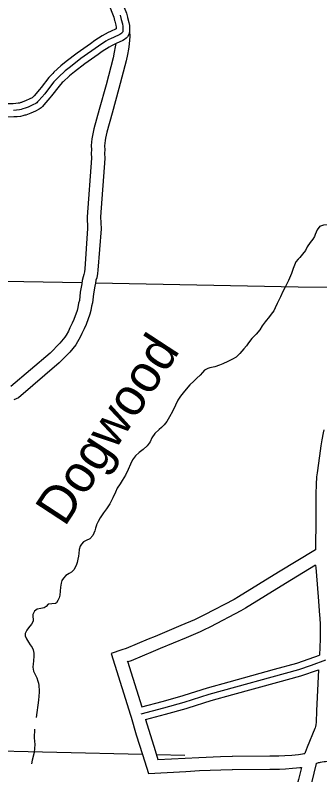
# Model space of a CAD drawing. Extents: x 1373094 to 1376427, y 1168361 to 1170494.
# Drawn here: x 1373788 to 1373845.2, y 1170254.2 to 1170397.1 of the extents above; entities that cross this region are included whole.
import ezdxf

# ---------------------------------------------------------------- set-up
doc = ezdxf.new("R2010")
doc.units = 0
doc.layers.add('R_Axis', color=7, linetype='Continuous')

msp = doc.modelspace()

# ---------------------------------------------------------------- linework, layer by layer
at = {"layer": 'R_Axis'}
for points in [[(1373806.18, 1170404.85), (1373806.33, 1170404.33), (1373807.4, 1170401.21), (1373808.14, 1170399.35), (1373808.44, 1170398.55), (1373808.85, 1170397.47), (1373809.05, 1170396.72)], [(1373803.7, 1170404.54), (1373803.72, 1170404.34), (1373803.95, 1170403.57), (1373805.05, 1170400.34), (1373805.81, 1170398.45), (1373806.1, 1170397.66), (1373806.47, 1170396.69), (1373806.64, 1170396.07)], [(1373807.66, 1170397.08), (1373807.87, 1170396.29), (1373808.1, 1170395.43), (1373808.17, 1170394.97), (1373808.19, 1170394.69), (1373808.21, 1170394.39), (1373808.2, 1170394.19), (1373808.19, 1170394.07), (1373808.16, 1170393.93), (1373808.07, 1170393.79), (1373807.98, 1170393.69), (1373807.79, 1170393.55), (1373807.6, 1170393.43), (1373806.4, 1170392.9), (1373805.99, 1170392.7), (1373805.44, 1170392.42), (1373804.98, 1170392.16), (1373803.61, 1170391.27), (1373800.32, 1170388.91), (1373798.32, 1170387.39), (1373797.33, 1170386.59), (1373796.09, 1170385.44), (1373795.24, 1170384.56), (1373793.82, 1170382.71), (1373793.5, 1170382.31)], [(1373809.05, 1170396.72), (1373809.08, 1170396.61), (1373809.33, 1170395.68), (1373809.41, 1170395.11), (1373809.44, 1170394.78), (1373809.46, 1170394.4), (1373809.45, 1170394.13), (1373809.43, 1170393.87), (1373809.32, 1170393.43), (1373809.07, 1170393.03), (1373808.82, 1170392.76), (1373808.49, 1170392.51), (1373808.18, 1170392.32), (1373806.93, 1170391.77), (1373806.54, 1170391.58), (1373806.03, 1170391.32), (1373805.63, 1170391.09), (1373804.32, 1170390.23), (1373803.54, 1170389.68)], [(1373806.64, 1170396.07), (1373806.67, 1170395.97), (1373806.88, 1170395.18), (1373806.93, 1170394.83), (1373806.95, 1170394.61), (1373806.95, 1170394.51), (1373805.87, 1170394.03), (1373805.43, 1170393.82), (1373804.84, 1170393.52), (1373804.32, 1170393.22), (1373802.9, 1170392.3), (1373802.09, 1170391.71)], [(1373809.44, 1170394.04), (1373809.47, 1170393), (1373809.45, 1170392.43), (1373809.38, 1170391.61), (1373809.22, 1170390.67), (1373809.04, 1170389.66), (1373808.81, 1170388.51), (1373807.44, 1170383.3), (1373806.17, 1170378.64), (1373805.16, 1170375.1), (1373804.94, 1170373.98), (1373804.85, 1170373.5), (1373804.81, 1170373), (1373804.76, 1170372.49), (1373804.77, 1170371.75), (1373804.75, 1170371.11), (1373804.77, 1170370.12), (1373803.99, 1170359.14), (1373804.08, 1170356.93), (1373803.5, 1170349.14), (1373803.42, 1170348.48), (1373803.28, 1170347.66), (1373803.13, 1170347.23), (1373803.02, 1170346.67), (1373802.9, 1170346.1), (1373802.66, 1170344.65), (1373802.48, 1170342.99), (1373802.32, 1170342.34), (1373802.16, 1170341.54), (1373802, 1170340.84), (1373801.3, 1170338.92), (1373800.92, 1170338.08), (1373800.5, 1170337.24), (1373800.19, 1170336.55), (1373799.69, 1170335.64), (1373799.32, 1170335.07), (1373798.21, 1170333.72), (1373796.2, 1170331.69), (1373788.55, 1170325.14), (1373788.13, 1170324.94), (1373787.67, 1170324.73)], [(1373806.87, 1170391.74), (1373806.75, 1170391.1), (1373806.58, 1170390.12), (1373806.38, 1170389.07), (1373805.03, 1170383.95), (1373803.76, 1170379.32), (1373802.73, 1170375.68), (1373802.49, 1170374.46), (1373802.37, 1170373.83), (1373802.32, 1170373.22), (1373802.26, 1170372.6), (1373802.27, 1170371.77), (1373802.25, 1170371.14), (1373802.27, 1170370.19), (1373801.49, 1170359.18), (1373801.57, 1170356.97), (1373801.01, 1170349.38), (1373800.95, 1170348.84), (1373800.85, 1170348.29), (1373800.71, 1170347.87), (1373800.57, 1170347.16), (1373800.45, 1170346.56), (1373800.18, 1170344.99), (1373800.01, 1170343.41), (1373799.88, 1170342.89), (1373799.71, 1170342.08), (1373799.59, 1170341.54), (1373798.99, 1170339.87), (1373798.66, 1170339.16), (1373798.24, 1170338.31), (1373797.95, 1170337.66), (1373797.54, 1170336.92), (1373797.3, 1170336.55), (1373796.35, 1170335.39), (1373794.5, 1170333.52), (1373787.16, 1170327.25)], [(1373802.09, 1170391.71), (1373799.58, 1170389.92), (1373797.55, 1170388.38), (1373796.51, 1170387.54), (1373795.21, 1170386.33), (1373795.01, 1170386.12)], [(1373803.54, 1170389.68), (1373801.06, 1170387.9), (1373799.09, 1170386.41), (1373798.15, 1170385.65), (1373796.96, 1170384.55), (1373796.81, 1170384.39)], [(1373795.01, 1170386.12), (1373794.29, 1170385.37), (1373792.84, 1170383.49), (1373792.53, 1170383.1), (1373791.49, 1170381.88), (1373791.29, 1170381.67), (1373791.19, 1170381.57), (1373791.13, 1170381.52), (1373790.72, 1170381.32), (1373789.9, 1170380.96), (1373789.41, 1170380.77), (1373789.12, 1170380.66)], [(1373796.81, 1170384.39), (1373796.19, 1170383.74), (1373794.8, 1170381.94), (1373794.46, 1170381.51), (1373793.35, 1170380.2), (1373793.06, 1170379.9), (1373792.82, 1170379.67), (1373792.47, 1170379.4), (1373791.78, 1170379.05), (1373790.86, 1170378.65), (1373790.29, 1170378.42), (1373789.94, 1170378.3)], [(1373793.5, 1170382.31), (1373792.42, 1170381.04), (1373792.17, 1170380.78), (1373792, 1170380.62), (1373791.8, 1170380.46), (1373791.25, 1170380.19), (1373790.38, 1170379.8), (1373789.85, 1170379.59), (1373789.4, 1170379.44), (1373789.08, 1170379.35), (1373788.74, 1170379.28), (1373788.19, 1170379.21), (1373787.63, 1170379.18)], [(1373789.12, 1170380.66), (1373789.02, 1170380.63), (1373788.78, 1170380.56), (1373788.54, 1170380.51), (1373788.08, 1170380.46), (1373787.58, 1170380.43), (1373786.56, 1170380.41), (1373780.78, 1170380.49)], [(1373789.94, 1170378.3), (1373789.78, 1170378.25), (1373789.38, 1170378.13), (1373788.94, 1170378.04), (1373788.3, 1170377.96), (1373787.67, 1170377.93), (1373786.56, 1170377.91), (1373780.75, 1170377.99)], [(1373845.19, 1170357.41), (1373845.96, 1170357.65), (1373846.96, 1170357.7), (1373847.75, 1170357.73), (1373848.99, 1170358.19)], [(1373845.19, 1170357.41), (1373844.72, 1170356.69), (1373844.34, 1170355.86), (1373844.18, 1170355.46), (1373843.87, 1170354.97), (1373843.38, 1170354.3), (1373842.86, 1170353.5), (1373842.49, 1170352.83), (1373841.97, 1170352.15), (1373841.48, 1170351.54), (1373841.16, 1170351.22), (1373840.68, 1170350.7), (1373840.44, 1170350.07), (1373840.17, 1170349.44), (1373839.9, 1170348.51), (1373839.33, 1170347.17), (1373839.15, 1170346.83), (1373838.72, 1170345.96), (1373838.26, 1170345.13), (1373837.8, 1170344.11), (1373837.22, 1170342.88), (1373836.84, 1170342.02), (1373836.55, 1170341.45), (1373836.07, 1170340.84), (1373835.73, 1170340.42), (1373834.95, 1170339.43), (1373834.36, 1170338.66), (1373833.96, 1170337.93), (1373833.26, 1170337.09), (1373832.42, 1170336.26), (1373831.81, 1170335.46), (1373831.43, 1170334.92), (1373830.93, 1170334.35), (1373830.16, 1170333.47), (1373829.47, 1170332.77), (1373828.78, 1170332.36), (1373827.89, 1170331.93), (1373827.01, 1170331.53), (1373826.37, 1170331.27), (1373825.46, 1170330.97), (1373824.88, 1170330.84), (1373824.56, 1170330.74), (1373824.13, 1170330.65), (1373823.52, 1170330.31), (1373823.17, 1170329.87), (1373822.71, 1170329.41), (1373822.08, 1170328.81), (1373821.51, 1170328.27), (1373820.76, 1170327.57), (1373819.76, 1170326.39), (1373819.01, 1170325.41), (1373818.51, 1170324.7), (1373818.08, 1170323.76), (1373817.53, 1170322.56), (1373816.98, 1170321.52), (1373816.45, 1170320.66), (1373815.98, 1170320.03), (1373815.45, 1170319.56), (1373815.03, 1170319.18), (1373814.21, 1170318.39), (1373813.66, 1170317.61), (1373813.32, 1170316.85), (1373812.77, 1170316.08), (1373812.03, 1170315.4), (1373811.26, 1170314.82), (1373810.59, 1170314.19), (1373809.98, 1170313.48), (1373809.6, 1170312.65), (1373809.2, 1170311.63), (1373808.68, 1170310.59), (1373808.08, 1170309.59), (1373807.66, 1170308.97), (1373807.14, 1170308.12), (1373806.79, 1170307.37), (1373806.29, 1170306.32), (1373805.73, 1170305.16), (1373805.11, 1170304.23), (1373804.56, 1170303.47), (1373803.94, 1170302.58), (1373803.57, 1170301.87), (1373803.22, 1170301.25), (1373803.22, 1170301.2), (1373803.03, 1170300.59), (1373802.94, 1170300.09), (1373802.76, 1170299.64), (1373802.52, 1170299.2), (1373802.01, 1170298.62), (1373801.29, 1170298.3), (1373800.81, 1170298.02), (1373800.4, 1170297.63), (1373800.19, 1170297.24), (1373800, 1170296.61), (1373799.93, 1170295.87), (1373799.84, 1170295.32), (1373799.75, 1170294.78), (1373799.63, 1170294.13), (1373799.4, 1170293.61), (1373799, 1170292.8), (1373798.53, 1170292.34), (1373798.07, 1170292.07), (1373797.44, 1170291.69)], [(1373757.2, 1170347.82), (1373764.02, 1170347.46), (1373800.48, 1170346.78)], [(1373803.03, 1170346.73), (1373841.16, 1170346.01)], [(1373841.16, 1170346.01), (1373848.74, 1170345.95)], [(1373845.95, 1170319.1), (1373845.85, 1170318.56), (1373845.59, 1170317.21), (1373845.42, 1170316.08), (1373845.15, 1170314.24), (1373844.68, 1170311), (1373844.61, 1170310.29)], [(1373844.61, 1170310.29), (1373844.59, 1170310.01), (1373844.53, 1170309.05), (1373844.45, 1170306.8), (1373844.44, 1170303.36), (1373844.43, 1170301.38)], [(1373844.43, 1170301.38), (1373844.42, 1170297.66), (1373844.38, 1170296.55)], [(1373844.38, 1170296.55), (1373837.44, 1170292.31)], [(1373844.41, 1170293.64), (1373838.75, 1170290.18)], [(1373844.41, 1170293.64), (1373844.45, 1170293.13), (1373844.5, 1170292.47)], [(1373837.44, 1170292.31), (1373829.93, 1170287.72)], [(1373844.5, 1170292.47), (1373844.98, 1170286.87), (1373845.18, 1170284.2), (1373845.2, 1170283.76)], [(1373797.44, 1170291.69), (1373797.02, 1170291.2), (1373796.69, 1170290.74), (1373796.58, 1170290.26), (1373796.48, 1170289.49), (1373796.42, 1170288.75), (1373796.34, 1170288.02), (1373796.21, 1170287.51), (1373795.95, 1170286.99), (1373795.7, 1170286.6), (1373795.51, 1170286.47), (1373794.83, 1170286.37), (1373794.14, 1170286.29), (1373793.76, 1170285.85), (1373793.38, 1170285.6), (1373792.74, 1170285.5), (1373792.07, 1170285.36), (1373791.61, 1170285), (1373791.27, 1170284.38), (1373791.27, 1170283.88), (1373791.32, 1170283.58), (1373791.35, 1170283.11), (1373791.04, 1170282.57), (1373790.43, 1170281.84), (1373790.11, 1170281.46), (1373789.85, 1170280.8), (1373789.84, 1170280.35), (1373790.09, 1170279.78), (1373790.43, 1170279.19), (1373790.77, 1170278.64), (1373791.15, 1170278.15), (1373791.32, 1170277.75), (1373791.46, 1170277.12), (1373791.45, 1170276.63), (1373791.42, 1170275.63), (1373791.31, 1170275.08), (1373791.28, 1170274.44), (1373791.42, 1170273.73), (1373791.66, 1170273.23), (1373792.02, 1170272.47), (1373792.22, 1170271.82), (1373792.32, 1170271.49), (1373792.38, 1170271.05), (1373792.42, 1170270.7), (1373792.43, 1170270.34), (1373792.45, 1170269.94), (1373792.45, 1170269.75), (1373792.36, 1170268.28)], [(1373838.75, 1170290.18), (1373831.24, 1170285.59)], [(1373829.93, 1170287.72), (1373829.11, 1170287.22), (1373823.52, 1170284.29), (1373822.26, 1170283.67)], [(1373831.24, 1170285.59), (1373830.34, 1170285.04), (1373824.65, 1170282.06), (1373823.35, 1170281.42)], [(1373822.26, 1170283.67), (1373821.66, 1170283.38), (1373819.11, 1170282.3), (1373814.23, 1170280.26)], [(1373845.2, 1170283.76), (1373845.25, 1170282.45), (1373845.28, 1170280.41), (1373845.28, 1170279.71), (1373845.13, 1170276.74)], [(1373823.35, 1170281.42), (1373822.69, 1170281.1), (1373820.08, 1170279.99), (1373815.19, 1170277.95)], [(1373814.23, 1170280.26), (1373812.94, 1170279.72), (1373808.81, 1170278.01), (1373807.97, 1170277.7), (1373805.99, 1170277.06), (1373806.68, 1170274.84)], [(1373815.19, 1170277.95), (1373813.9, 1170277.41), (1373809.73, 1170275.68), (1373809.11, 1170275.45), (1373809.07, 1170275.58)], [(1373836.68, 1170274.08), (1373840.91, 1170275.25), (1373843.21, 1170276.03), (1373845.13, 1170276.74)], [(1373806.68, 1170274.84), (1373809.31, 1170266.44)], [(1373809.07, 1170275.58), (1373811.75, 1170267.01)], [(1373811.61, 1170265.69), (1373815.9, 1170266.81), (1373819.7, 1170267.91), (1373824.44, 1170269.4), (1373841.28, 1170274.05), (1373843.63, 1170274.85), (1373846.34, 1170275.86)], [(1373828.2, 1170271.73), (1373836.68, 1170274.08)], [(1373837.34, 1170271.67), (1373841.65, 1170272.86), (1373844.99, 1170274)], [(1373844.99, 1170274), (1373844.61, 1170266.29)], [(1373819.72, 1170269.22), (1373824.08, 1170270.6), (1373828.2, 1170271.73)], [(1373828.86, 1170269.32), (1373837.34, 1170271.67)], [(1373811.75, 1170267.01), (1373815.56, 1170268.02), (1373819.34, 1170269.1), (1373819.72, 1170269.22)], [(1373820.47, 1170266.84), (1373824.79, 1170268.2), (1373828.86, 1170269.32)], [(1373792.36, 1170268.28), (1373791.89, 1170265.01)], [(1373809.31, 1170266.44), (1373809.56, 1170265.64), (1373809.73, 1170265.09), (1373810.7, 1170261.76), (1373811.88, 1170258.02)], [(1373812.43, 1170264.61), (1373816.23, 1170265.61), (1373820.06, 1170266.71), (1373820.47, 1170266.84)], [(1373844.61, 1170266.29), (1373844.5, 1170264.11), (1373844.45, 1170263.61), (1373844.41, 1170263.33), (1373844.35, 1170263.09), (1373844.29, 1170262.94), (1373842.81, 1170259.44), (1373842.44, 1170258.44), (1373842.39, 1170258.25)], [(1373812.43, 1170264.61), (1373814.26, 1170258.77)], [(1373791.6, 1170262.83), (1373791.5, 1170261.2), (1373791.65, 1170259.94), (1373791.5, 1170258.4), (1373791.17, 1170256.99), (1373791.04, 1170256.3)], [(1373761.58, 1170259.3), (1373763.53, 1170259.25), (1373811.85, 1170258.1)], [(1373811.88, 1170258.02), (1373812.98, 1170254.49), (1373820.02, 1170254.87)], [(1373814.26, 1170258.77), (1373814.79, 1170257.09), (1373819.88, 1170257.37)], [(1373814.49, 1170258.04), (1373819.85, 1170257.91)], [(1373819.88, 1170257.37), (1373822.49, 1170257.51), (1373826.55, 1170257.67), (1373828.72, 1170257.71)], [(1373828.72, 1170257.71), (1373828.78, 1170257.71), (1373835.8, 1170257.77), (1373837.19, 1170257.79), (1373837.48, 1170257.81)], [(1373837.48, 1170257.81), (1373838.61, 1170257.86), (1373839.92, 1170257.95), (1373840.6, 1170258.01), (1373841.21, 1170258.06), (1373841.58, 1170258.11), (1373841.98, 1170258.17), (1373842.23, 1170258.21), (1373842.39, 1170258.25)], [(1373844.5, 1170256.37), (1373843.64, 1170252.71), (1373842.87, 1170250.11), (1373842.46, 1170248.94)], [(1373844.5, 1170256.37), (1373844.95, 1170256.52), (1373845.14, 1170256.57), (1373845.35, 1170256.61), (1373845.65, 1170256.66), (1373846, 1170256.71), (1373846.27, 1170256.74), (1373846.99, 1170256.81), (1373847.73, 1170256.86), (1373848.12, 1170256.87), (1373852.4, 1170257)], [(1373820.02, 1170254.87), (1373822.6, 1170255.01), (1373826.62, 1170255.17), (1373828.76, 1170255.21)], [(1373828.76, 1170255.21), (1373828.81, 1170255.21), (1373835.84, 1170255.27), (1373837.28, 1170255.3), (1373837.6, 1170255.31)], [(1373837.6, 1170255.31), (1373838.75, 1170255.37), (1373840.1, 1170255.46), (1373840.81, 1170255.52), (1373841.47, 1170255.58), (1373841.75, 1170255.61)], [(1373841.75, 1170255.61), (1373841.22, 1170253.35), (1373840.49, 1170250.88), (1373840.1, 1170249.75)]]:
    msp.add_lwpolyline(points, dxfattribs=at)

# ---------------------------------------------------------------- texts
msp.add_text('Dogwood', height=7.04, rotation=56.8097, dxfattribs=at).set_placement((1373797.26, 1170300.72))

doc.saveas('drawing.dxf')
